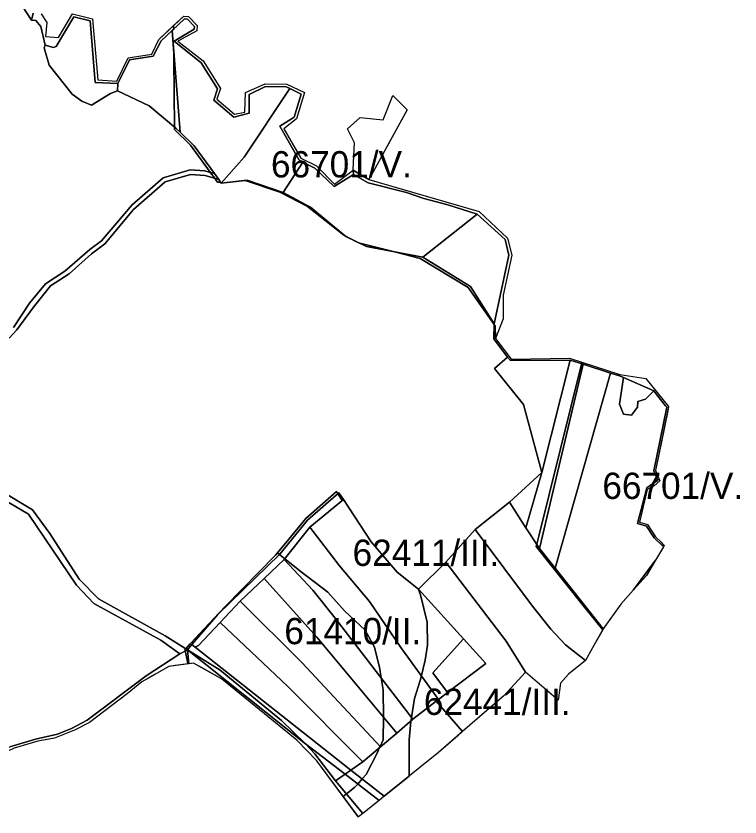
# Model space of a CAD drawing. Extents: x -522079 to -518792, y -1142400 to -1139961.
# Drawn here: x -519204.8 to -518792, y -1141827.7 to -1141371.1 of the extents above; entities that cross this region are included whole.
import ezdxf

# ---------------------------------------------------------------- set-up
doc = ezdxf.new("R2010")
doc.units = 0
for name, color, linetype in [('Hranice parcel', 7, 'Continuous'), ('Parcelní čísla', 7, 'Continuous'), ('Poz předměty', 7, 'Continuous'), ('Vnitřní kresba', 7, 'Continuous'), ('Značky bodu BP', 7, 'Continuous'), ('Značky budov', 7, 'Continuous')]:
    doc.layers.add(name, color=color, linetype=linetype)

msp = doc.modelspace()

# ---------------------------------------------------------------- linework, layer by layer
at = {"layer": 'Hranice parcel'}
msp.add_lwpolyline([(-519206.19, -1141548.7), (-519197.16, -1141534.83), (-519187.98, -1141523.67), (-519176.92, -1141516.46), (-519162.77, -1141504.09), (-519156, -1141499.24), (-519138.46, -1141478.73), (-519120.93, -1141463.32), (-519105.52, -1141458.68), (-519097.28, -1141459.27), (-519091.6, -1141460.78), (-519089.22, -1141464.23), (-519097.02, -1141461.95), (-519105.2, -1141461.4), (-519119.76, -1141465.66), (-519137.74, -1141481.36), (-519154.09, -1141500.95), (-519161.65, -1141506.59), (-519174.38, -1141518.14), (-519185.11, -1141524.98), (-519194.87, -1141536.97), (-519204.3, -1141549.93), (-519208.65, -1141554.69)], dxfattribs=at)
for points in [[(-519215.97, -1141644.42), (-519234.03, -1141639.34), (-519247.24, -1141637.55), (-519267.72, -1141635.03), (-519278.79, -1141629.39), (-519283.88, -1141624.46), (-519281.83, -1141620.82), (-519276.07, -1141627.44), (-519266.93, -1141631.65), (-519236.73, -1141634.83), (-519229.49, -1141636.68), (-519214.22, -1141641.4), (-519195.4, -1141652.58), (-519185.55, -1141666.07), (-519168.83, -1141692.07), (-519157.76, -1141703.36), (-519119.77, -1141724.36), (-519107.07, -1141732.42), (-519111.34, -1141734.71), (-519122.24, -1141726.88), (-519160.32, -1141706.01), (-519170.28, -1141695.6), (-519197.57, -1141654.98)], [(-519100.73, -1141730.04), (-519102.66, -1141730.9), (-519104.58, -1141729.38), (-519089.65, -1141712.19), (-519054.42, -1141677.83), (-519038.58, -1141658.51), (-519020.66, -1141642.94), (-519018.14, -1141646.74), (-519037.2, -1141662.52), (-519051.93, -1141680.89), (-519063.3, -1141691.75), (-519076.93, -1141704.76), (-519088.31, -1141716.77)], [(-519053.38, -1141772.67), (-519088.35, -1141744.1), (-519107.07, -1141732.42), (-519104.58, -1141729.38), (-519102.66, -1141730.9), (-519013.82, -1141800.95), (-519017.2, -1141803.32), (-519039.72, -1141785.92)], [(-519192.31, -1141784.44), (-519205.85, -1141788.49), (-519209.88, -1141790.38), (-519211, -1141789.08), (-519208.31, -1141787.64), (-519193.63, -1141783.33), (-519181.21, -1141780.54), (-519173.18, -1141777.23), (-519164.17, -1141772.59), (-519130.56, -1141747.22), (-519111.34, -1141734.71), (-519107.07, -1141732.42), (-519106.29, -1141740.33), (-519117.64, -1141741.85), (-519132.98, -1141750.7), (-519141.38, -1141757.45), (-519162.82, -1141773.79), (-519171.52, -1141778.29), (-519182.83, -1141782.69)], [(-519053.38, -1141772.67), (-519039.72, -1141785.92), (-519107.07, -1141732.42), (-519088.35, -1141744.1)], [(-518994.87, -1141815.89), (-518997.83, -1141818.27), (-519017.2, -1141803.32), (-519013.82, -1141800.95)]]:
    msp.add_lwpolyline(points, close=True, dxfattribs=at)
at = {"layer": 'Parcelní čísla'}
for points in [[(-519037.2, -1141662.52), (-519020.32, -1141684.47), (-519003.26, -1141704.92), (-518985.35, -1141731.05), (-518963.82, -1141760.65), (-518965.15, -1141761.66), (-518978.59, -1141771.9), (-519022.75, -1141714.32), (-519035.63, -1141698.35), (-519051.93, -1141680.89)], [(-518978.59, -1141771.9), (-518987.69, -1141779.96), (-519033.2, -1141725.1), (-519063.3, -1141691.75), (-519051.93, -1141680.89), (-519035.63, -1141698.35), (-519022.75, -1141714.32)], [(-519063.3, -1141691.75), (-519033.2, -1141725.1), (-518987.69, -1141779.96), (-518996.96, -1141787.68), (-519041.86, -1141739.72), (-519076.93, -1141704.76)], [(-519076.93, -1141704.76), (-519041.86, -1141739.72), (-518996.96, -1141787.68), (-519007.07, -1141796.21), (-519049.77, -1141753.31), (-519088.31, -1141716.77)], [(-519100.73, -1141730.04), (-519088.31, -1141716.77), (-519049.77, -1141753.31), (-519007.07, -1141796.21), (-519013.82, -1141800.95), (-519102.66, -1141730.9)], [(-519034.33, -1141791.67), (-519022.6, -1141807.12), (-519007.06, -1141825.69), (-519009.58, -1141827.71), (-519033.21, -1141795.69), (-519044.72, -1141783.93), (-519087.6, -1141748.94), (-519103.5, -1141739.96), (-519106.29, -1141740.33), (-519107.07, -1141732.42), (-519039.72, -1141785.92)], [(-518978.59, -1141771.9), (-518965.15, -1141761.66), (-518950.14, -1141779.05), (-518963.91, -1141791), (-518994.87, -1141815.89), (-519013.82, -1141800.95), (-519007.07, -1141796.21), (-518996.96, -1141787.68), (-518987.69, -1141779.96)], [(-519039.72, -1141785.92), (-519017.2, -1141803.32), (-519022.6, -1141807.12), (-519034.33, -1141791.67)], [(-519022.6, -1141807.12), (-519017.2, -1141803.32), (-518997.83, -1141818.27), (-519007.06, -1141825.69)]]:
    msp.add_lwpolyline(points, close=True, dxfattribs=at)
at = {"layer": 'Poz předměty'}
for points in [[(-519012.53, -1141459.04), (-519012.34, -1141454.52), (-519011.87, -1141443.33), (-519015.74, -1141435.38), (-519008.63, -1141428.83), (-518995.53, -1141430.25), (-518989.97, -1141416.33), (-518981.74, -1141424.63), (-518994.55, -1141447.83), (-519001.41, -1141460.26), (-519003.59, -1141464.2), (-519005.83, -1141462.95)], [(-518906.3, -1141674.57), (-518881.49, -1141569.59), (-518865.88, -1141574.59), (-518897.41, -1141685.82)], [(-518845.18, -1141639.97), (-518850.48, -1141660.34), (-518845.32, -1141661.82), (-518840.87, -1141668.48), (-518835.69, -1141673.66), (-518840.27, -1141681.38), (-518852.72, -1141698.29), (-518859.88, -1141706.38), (-518869.99, -1141720.5), (-518897.41, -1141685.82), (-518865.88, -1141574.59), (-518860.8, -1141576.22), (-518858.5, -1141577.22), (-518860.72, -1141592.27), (-518858.42, -1141598.04), (-518853.84, -1141598.54), (-518850.43, -1141594.07), (-518850.24, -1141590.84), (-518845.96, -1141589.42), (-518841.19, -1141584.77), (-518839.43, -1141586.95), (-518834.47, -1141593.24), (-518833.75, -1141593.98), (-518841.11, -1141630.32), (-518838.85, -1141635.75)], [(-518853.84, -1141598.54), (-518858.42, -1141598.04), (-518860.72, -1141592.27), (-518858.5, -1141577.22), (-518841.19, -1141584.77), (-518845.96, -1141589.42), (-518850.24, -1141590.84), (-518850.43, -1141594.07)], [(-519037.2, -1141662.52), (-519018.14, -1141646.74), (-519002.22, -1141670.75), (-518987.45, -1141688.21), (-518975.25, -1141697.8), (-518949.63, -1141726.06), (-518967.09, -1141745.55), (-518958.75, -1141756.79), (-518963.82, -1141760.65), (-518985.35, -1141731.05), (-519003.26, -1141704.92), (-519020.32, -1141684.47)], [(-518845.39, -1141690.02), (-518852.72, -1141698.29), (-518840.27, -1141681.38)]]:
    msp.add_lwpolyline(points, close=True, dxfattribs=at)
at = {"layer": 'Vnitřní kresba'}
for points in [[(-519194.96, -1141369.43), (-519195.98, -1141373.38), (-519201.22, -1141365.24)], [(-519190.42, -1141369.81), (-519187.2, -1141374.82), (-519188.01, -1141382.78), (-519180.54, -1141383.29), (-519172.49, -1141369.75), (-519161.16, -1141372.68), (-519158.19, -1141407.51), (-519147.23, -1141408.12), (-519140.85, -1141394.82), (-519127.25, -1141392.73), (-519123.4, -1141384.39), (-519109.18, -1141371.2), (-519106.36, -1141371.37), (-519101.55, -1141376.47), (-519101.7, -1141379.43), (-519112.59, -1141385.36), (-519098.12, -1141396.65), (-519088.18, -1141412.32), (-519090.32, -1141418.48), (-519080.26, -1141427.02), (-519074.35, -1141425.83), (-519073.85, -1141414.66), (-519062.78, -1141409.81), (-519050.33, -1141409.98), (-519040.39, -1141414.74), (-519044.82, -1141429.69), (-519052, -1141435.32), (-519042.3, -1141452.19), (-519033.46, -1141456.53), (-519023.29, -1141466.86), (-519012.53, -1141459.04), (-519012.3, -1141461.46), (-519023.36, -1141468.17), (-519034.35, -1141457.76), (-519041.21, -1141454.39), (-519043.38, -1141453.33), (-519054.33, -1141433.88), (-519046.13, -1141428.81), (-519042.19, -1141415.54), (-519048.65, -1141412.42), (-519050.68, -1141411.48), (-519062.49, -1141411.31), (-519071.92, -1141415.76), (-519071.77, -1141426.39), (-519080.67, -1141428.64), (-519092.08, -1141418.96), (-519089.83, -1141412.51), (-519099.25, -1141397.67), (-519114.56, -1141385.44), (-519103.16, -1141378.52), (-519103.08, -1141377.03), (-519107.04, -1141372.83), (-519108.63, -1141372.74), (-519115.78, -1141379.37), (-519122.09, -1141385.22), (-519126.66, -1141393.95), (-519140.08, -1141396.13), (-519146.7, -1141409.56), (-519159.57, -1141408.94), (-519162.56, -1141373.86), (-519171.77, -1141371.48), (-519181.87, -1141388.46), (-519183.39, -1141388.93), (-519188.19, -1141387.74), (-519190.53, -1141377.07), (-519193.48, -1141373.59), (-519195.98, -1141373.38), (-519194.96, -1141369.43)]]:
    msp.add_lwpolyline(points, dxfattribs=at)
msp.add_lwpolyline([(-518841.19, -1141584.77), (-518858.5, -1141577.22), (-518860.8, -1141576.22), (-518865.88, -1141574.59), (-518881.49, -1141569.59), (-518888.92, -1141567.21), (-518922.95, -1141567.54), (-518924.52, -1141565.49), (-518932.45, -1141555.15), (-518932.13, -1141546.59), (-518923.9, -1141507.34), (-518925.88, -1141498.42), (-518941.87, -1141484.11), (-518958.68, -1141478.71), (-518972.22, -1141475.1), (-518982.13, -1141471.67), (-519003.93, -1141466.26), (-519012.3, -1141461.46), (-519012.53, -1141459.04), (-519005.83, -1141462.95), (-519003.59, -1141464.2), (-518940.71, -1141482.48), (-518924.49, -1141497.8), (-518922.06, -1141507.35), (-518927.02, -1141530.23), (-518927.11, -1141543.74), (-518931.43, -1141555), (-518922.51, -1141566.63), (-518889.18, -1141566.18), (-518860.53, -1141575.36), (-518845.76, -1141577.71), (-518832.78, -1141593.74), (-518840.17, -1141630.23), (-518837.74, -1141636.08), (-518840.9, -1141638.87), (-518844.96, -1141640.98), (-518849.41, -1141659.71), (-518844.75, -1141661.05), (-518840.16, -1141667.91), (-518837.05, -1141671.02), (-518835.83, -1141672.48), (-518835.18, -1141672.79), (-518835.69, -1141673.66), (-518840.87, -1141668.48), (-518845.32, -1141661.82), (-518850.48, -1141660.34), (-518845.18, -1141639.97), (-518838.85, -1141635.75), (-518841.11, -1141630.32), (-518833.75, -1141593.98), (-518834.47, -1141593.24), (-518839.43, -1141586.95)], close=True, dxfattribs=at)
at = {"layer": 'Značky bodu BP'}
msp.add_lwpolyline([(-519190.42, -1141369.81), (-519187.2, -1141374.82), (-519188.01, -1141382.78), (-519180.54, -1141383.29), (-519172.49, -1141369.75), (-519161.16, -1141372.68), (-519158.19, -1141407.51), (-519147.23, -1141408.12), (-519140.85, -1141394.82), (-519127.25, -1141392.73), (-519123.4, -1141384.39), (-519114.91, -1141376.51), (-519114.89, -1141378.55), (-519115.78, -1141379.37), (-519114.79, -1141392.16), (-519114.76, -1141395.66), (-519114.45, -1141434.34), (-519114.44, -1141435.73), (-519105.32, -1141444.7), (-519093.99, -1141460.14), (-519093.82, -1141460.38), (-519091.51, -1141463.56), (-519091.05, -1141464.19), (-519089.82, -1141465.88), (-519088.81, -1141465.79), (-519088.18, -1141465.73), (-519087.76, -1141466.33), (-519074.1, -1141464.81), (-519054.45, -1141471.42), (-519038.62, -1141479.75), (-519017.88, -1141496.05), (-519017.44, -1141496.27), (-519011.01, -1141499.58), (-519009.72, -1141500.25), (-519009.51, -1141500.31), (-518988.31, -1141505.68), (-518974.38, -1141509.22), (-518947.06, -1141525.93), (-518932.14, -1141546.87), (-518931.94, -1141547.15), (-518931.68, -1141547.51), (-518931.43, -1141555), (-518922.51, -1141566.63), (-518889.18, -1141566.18), (-518882.12, -1141568.44), (-518882.2, -1141568.75), (-518882.42, -1141569.64), (-518906.77, -1141667.62), (-518907.9, -1141672.18), (-518908.23, -1141673.5), (-518881.36, -1141707.08), (-518870.25, -1141720.96), (-518876.08, -1141731.29), (-518880.1, -1141738.42), (-518889.83, -1141746.28), (-518894.38, -1141751.49), (-518895.73, -1141761.19), (-518914.26, -1141745.22), (-518926.6, -1141758.63), (-518950.14, -1141779.05), (-518965.15, -1141761.66), (-518963.82, -1141760.65), (-518958.75, -1141756.79), (-518967.09, -1141745.55), (-518949.63, -1141726.06), (-518975.25, -1141697.8), (-518987.45, -1141688.21), (-519002.22, -1141670.75), (-519018.14, -1141646.74), (-519018.79, -1141647.28), (-519019.83, -1141645.67), (-519021.25, -1141643.45), (-519022.09, -1141642.15), (-519039.51, -1141657.59), (-519049.19, -1141669.31), (-519055.71, -1141677.2), (-519056.76, -1141678.48), (-519085.6, -1141707.64), (-519097.6, -1141720.57), (-519105.12, -1141728.66), (-519105.58, -1141729.16), (-519108.03, -1141731.81), (-519108.23, -1141732.02), (-519108.46, -1141732.26), (-519108.37, -1141732.68), (-519108.29, -1141733.07), (-519107.07, -1141739.1), (-519106.85, -1141740.41), (-519112.49, -1141741.16), (-519114, -1141741.36), (-519117.64, -1141741.85), (-519125.57, -1141746.42), (-519129.17, -1141748.5), (-519132.98, -1141750.7), (-519141.38, -1141757.45), (-519162.82, -1141773.79), (-519171.52, -1141778.29), (-519182.83, -1141782.69), (-519185.92, -1141783.26), (-519192.31, -1141784.44), (-519205.85, -1141788.49)], dxfattribs=at)
for points in [[(-519109.18, -1141371.2), (-519106.36, -1141371.37), (-519101.55, -1141376.47), (-519101.7, -1141379.43), (-519112.59, -1141385.36), (-519098.12, -1141396.65), (-519088.18, -1141412.32), (-519090.32, -1141418.48), (-519080.26, -1141427.02), (-519074.35, -1141425.83), (-519073.85, -1141414.66), (-519062.78, -1141409.81), (-519050.33, -1141409.98), (-519040.39, -1141414.74), (-519044.82, -1141429.69), (-519052, -1141435.32), (-519042.3, -1141452.19), (-519033.46, -1141456.53), (-519023.29, -1141466.86), (-519012.53, -1141459.04), (-519012.34, -1141454.52), (-519011.87, -1141443.33), (-519015.74, -1141435.38), (-519008.63, -1141428.83), (-518995.53, -1141430.25), (-518989.97, -1141416.33), (-518981.74, -1141424.63), (-518994.04, -1141446.9), (-518994.26, -1141447.3), (-518994.55, -1141447.83), (-519001.41, -1141460.26), (-519003.59, -1141464.2), (-518940.71, -1141482.48), (-518924.49, -1141497.8), (-518922.06, -1141507.35), (-518927.02, -1141530.23), (-518927.11, -1141543.74), (-518931.43, -1141555), (-518931.68, -1141547.51), (-518931.94, -1141547.15), (-518932.14, -1141546.87), (-518947.06, -1141525.93), (-518974.38, -1141509.22), (-518988.31, -1141505.68), (-519009.51, -1141500.31), (-519009.72, -1141500.25), (-519011.01, -1141499.58), (-519017.44, -1141496.27), (-519017.88, -1141496.05), (-519038.62, -1141479.75), (-519054.45, -1141471.42), (-519074.1, -1141464.81), (-519087.76, -1141466.33), (-519088.18, -1141465.73), (-519088.81, -1141465.79), (-519089.82, -1141465.88), (-519091.05, -1141464.19), (-519091.51, -1141463.56), (-519093.82, -1141460.38), (-519093.99, -1141460.14), (-519105.32, -1141444.7), (-519114.44, -1141435.73), (-519114.45, -1141434.34), (-519114.76, -1141395.66), (-519114.79, -1141392.16), (-519115.78, -1141379.37), (-519114.89, -1141378.55), (-519114.91, -1141376.51)], [(-518832.78, -1141593.74), (-518833.26, -1141596.09), (-518837.06, -1141614.85), (-518840.17, -1141630.23), (-518837.74, -1141636.08), (-518840.9, -1141638.87), (-518844.96, -1141640.98), (-518849.41, -1141659.71), (-518844.75, -1141661.05), (-518840.16, -1141667.91), (-518837.05, -1141671.02), (-518835.83, -1141672.48), (-518835.18, -1141672.79), (-518835.69, -1141673.66), (-518840.27, -1141681.38), (-518845.39, -1141690.02), (-518852.72, -1141698.29), (-518859.88, -1141706.38), (-518869.99, -1141720.5), (-518870.25, -1141720.96), (-518881.36, -1141707.08), (-518908.23, -1141673.5), (-518907.9, -1141672.18), (-518906.77, -1141667.62), (-518882.42, -1141569.64), (-518882.2, -1141568.75), (-518882.12, -1141568.44), (-518860.53, -1141575.36), (-518845.76, -1141577.71)], [(-519009.65, -1141827.61), (-519018.17, -1141816.07), (-519016.34, -1141814.6), (-519011.8, -1141810.95), (-519011.11, -1141810.19), (-519009.96, -1141808.91), (-519007.37, -1141806.04), (-519005.08, -1141803.51), (-518999.07, -1141791.8), (-518997.47, -1141788.11), (-518997.18, -1141787.44), (-518995.54, -1141783.65), (-518995.18, -1141770.9), (-518995.54, -1141755.28), (-518996.62, -1141748.38), (-518997.57, -1141742.39), (-518997.66, -1141741.8), (-519000.49, -1141730.81), (-519005.79, -1141721.24), (-519017.45, -1141710.24), (-519027, -1141699.6), (-519042.2, -1141687.9), (-519051.59, -1141680.46), (-519054.64, -1141678.04), (-519055.71, -1141677.2), (-519049.19, -1141669.31), (-519039.51, -1141657.59), (-519022.09, -1141642.15), (-519021.25, -1141643.45), (-519019.83, -1141645.67), (-519018.79, -1141647.28), (-519018.14, -1141646.74), (-519002.22, -1141670.75), (-518987.45, -1141688.21), (-518975.25, -1141697.8), (-518975.03, -1141698.5), (-518974.24, -1141700.97), (-518970.44, -1141716.62), (-518970.09, -1141729.75), (-518971.5, -1141738.26), (-518973.65, -1141747.14), (-518974.33, -1141749.96), (-518977.51, -1141760.25), (-518979.25, -1141771.03), (-518979.53, -1141772.73), (-518979.63, -1141773.36), (-518980.69, -1141783.65), (-518980.69, -1141792.87), (-518980.69, -1141800.95), (-518980.69, -1141803.93), (-518980.69, -1141804.49), (-518994.87, -1141815.89), (-518997.83, -1141818.27), (-519007.06, -1141825.69), (-519009.58, -1141827.71)], [(-519103.5, -1141739.96), (-519104.73, -1141740.12), (-519106.29, -1141740.33), (-519106.85, -1141740.41), (-519107.07, -1141739.1), (-519108.29, -1141733.07), (-519108.37, -1141732.68), (-519108.46, -1141732.26), (-519108.23, -1141732.02), (-519108.03, -1141731.81), (-519105.58, -1141729.16), (-519105.12, -1141728.66), (-519097.6, -1141720.57), (-519085.6, -1141707.64), (-519056.76, -1141678.48), (-519055.71, -1141677.2), (-519054.64, -1141678.04), (-519051.59, -1141680.46), (-519042.2, -1141687.9), (-519027, -1141699.6), (-519017.45, -1141710.24), (-519005.79, -1141721.24), (-519000.49, -1141730.81), (-518997.66, -1141741.8), (-518997.57, -1141742.39), (-518996.62, -1141748.38), (-518995.54, -1141755.28), (-518995.18, -1141770.9), (-518995.54, -1141783.65), (-518997.18, -1141787.44), (-518997.47, -1141788.11), (-518999.07, -1141791.8), (-519005.08, -1141803.51), (-519007.37, -1141806.04), (-519009.96, -1141808.91), (-519011.11, -1141810.19), (-519011.8, -1141810.95), (-519016.34, -1141814.6), (-519018.17, -1141816.07), (-519033.21, -1141795.69), (-519044.72, -1141783.93), (-519087.6, -1141748.94), (-519096.93, -1141743.67), (-519096.96, -1141743.65)], [(-518952.9, -1141781.45), (-518963.91, -1141791), (-518994.87, -1141815.89), (-518980.69, -1141804.49), (-518980.69, -1141803.93), (-518980.69, -1141800.95), (-518980.69, -1141792.87), (-518980.69, -1141783.65), (-518979.63, -1141773.36), (-518979.53, -1141772.73), (-518979.25, -1141771.03), (-518977.51, -1141760.25), (-518974.33, -1141749.96), (-518973.65, -1141747.14), (-518971.5, -1141738.26), (-518970.09, -1141729.75), (-518970.44, -1141716.62), (-518974.24, -1141700.97), (-518975.03, -1141698.5), (-518975.25, -1141697.8), (-518949.63, -1141726.06), (-518967.09, -1141745.55), (-518958.75, -1141756.79), (-518963.82, -1141760.65), (-518965.15, -1141761.66), (-518950.14, -1141779.05), (-518952.9, -1141781.44)]]:
    msp.add_lwpolyline(points, close=True, dxfattribs=at)
at = {"layer": 'Značky budov'}
for points in [[(-519201.22, -1141365.24), (-519195.98, -1141373.38), (-519193.48, -1141373.59), (-519190.53, -1141377.07), (-519188.19, -1141387.74), (-519188.81, -1141389.21), (-519185.95, -1141399.11), (-519172.73, -1141415.6), (-519167.27, -1141419.59), (-519161.79, -1141421.83), (-519150.96, -1141415.24), (-519146.88, -1141413.75), (-519128.84, -1141422.33), (-519113.73, -1141434.94), (-519111.28, -1141437.32), (-519103.24, -1141445.12), (-519091.6, -1141460.78), (-519097.28, -1141459.27), (-519105.52, -1141458.68), (-519120.93, -1141463.32), (-519138.46, -1141478.73), (-519156, -1141499.24), (-519162.77, -1141504.09), (-519176.92, -1141516.46), (-519187.98, -1141523.67), (-519197.16, -1141534.83), (-519206.19, -1141548.7)], [(-519208.65, -1141554.69), (-519204.3, -1141549.93), (-519194.87, -1141536.97), (-519185.11, -1141524.98), (-519174.38, -1141518.14), (-519161.65, -1141506.59), (-519154.09, -1141500.95), (-519137.74, -1141481.36), (-519119.76, -1141465.66), (-519105.2, -1141461.4), (-519097.02, -1141461.95), (-519089.22, -1141464.23), (-519087.76, -1141466.33), (-519073.04, -1141464.69), (-519052.51, -1141471.71), (-519036.96, -1141480), (-519016.8, -1141496.81), (-519004.9, -1141502.52), (-518972.83, -1141508.64), (-518945.58, -1141525.34), (-518932.13, -1141546.59), (-518932.45, -1141555.15), (-518924.52, -1141565.49), (-518931.99, -1141572.05), (-518915.44, -1141592.52), (-518904.97, -1141631.37), (-518923.48, -1141648.24), (-518942.97, -1141663.76), (-518959.67, -1141682.43), (-518975.25, -1141697.8), (-518987.45, -1141688.21), (-519002.22, -1141670.75), (-519018.14, -1141646.74), (-519020.66, -1141642.94), (-519038.58, -1141658.51), (-519054.42, -1141677.83), (-519089.65, -1141712.19), (-519104.58, -1141729.38), (-519107.07, -1141732.42), (-519119.77, -1141724.36), (-519157.76, -1141703.36), (-519168.83, -1141692.07), (-519185.55, -1141666.07), (-519195.4, -1141652.58), (-519214.22, -1141641.4)], [(-519215.97, -1141644.42), (-519197.57, -1141654.98), (-519170.28, -1141695.6), (-519160.32, -1141706.01), (-519122.24, -1141726.88), (-519111.34, -1141734.71), (-519130.56, -1141747.22), (-519164.17, -1141772.59), (-519173.18, -1141777.23), (-519181.21, -1141780.54), (-519193.63, -1141783.33), (-519208.31, -1141787.64)]]:
    msp.add_lwpolyline(points, dxfattribs=at)
for points in [[(-519167.27, -1141419.59), (-519172.73, -1141415.6), (-519185.95, -1141399.11), (-519188.81, -1141389.21), (-519188.19, -1141387.74), (-519183.39, -1141388.93), (-519181.87, -1141388.46), (-519171.77, -1141371.48), (-519162.56, -1141373.86), (-519159.57, -1141408.94), (-519146.7, -1141409.56), (-519146.88, -1141413.75), (-519150.96, -1141415.24), (-519161.79, -1141421.83)], [(-519115.78, -1141379.37), (-519108.63, -1141372.74), (-519107.04, -1141372.83), (-519103.08, -1141377.03), (-519103.16, -1141378.52), (-519114.56, -1141385.44), (-519099.25, -1141397.67), (-519089.83, -1141412.51), (-519092.08, -1141418.96), (-519080.67, -1141428.64), (-519071.77, -1141426.39), (-519071.92, -1141415.76), (-519062.49, -1141411.31), (-519050.68, -1141411.48), (-519048.65, -1141412.42), (-519074.76, -1141451.52), (-519087.76, -1141466.33), (-519089.22, -1141464.23), (-519091.6, -1141460.78), (-519103.24, -1141445.12), (-519111.28, -1141437.32)], [(-519113.73, -1141434.94), (-519128.84, -1141422.33), (-519146.88, -1141413.75), (-519146.7, -1141409.56), (-519140.08, -1141396.13), (-519126.66, -1141393.95), (-519122.09, -1141385.22), (-519115.78, -1141379.37), (-519111.28, -1141437.32)], [(-519048.65, -1141412.42), (-519042.19, -1141415.54), (-519046.13, -1141428.81), (-519054.33, -1141433.88), (-519043.38, -1141453.33), (-519041.21, -1141454.39), (-519052.51, -1141471.71), (-519073.04, -1141464.69), (-519087.76, -1141466.33), (-519074.76, -1141451.52)], [(-518941.87, -1141484.11), (-518972.83, -1141508.64), (-519004.9, -1141502.52), (-519016.8, -1141496.81), (-519036.96, -1141480), (-519052.51, -1141471.71), (-519041.21, -1141454.39), (-519034.35, -1141457.76), (-519023.36, -1141468.17), (-519012.3, -1141461.46), (-519003.93, -1141466.26), (-518982.13, -1141471.67), (-518972.22, -1141475.1), (-518958.68, -1141478.71)], [(-518932.13, -1141546.59), (-518945.58, -1141525.34), (-518972.83, -1141508.64), (-518941.87, -1141484.11), (-518925.88, -1141498.42), (-518923.9, -1141507.34)], [(-518888.92, -1141567.21), (-518904.97, -1141631.37), (-518915.44, -1141592.52), (-518931.99, -1141572.05), (-518924.52, -1141565.49), (-518922.95, -1141567.54)], [(-518906.3, -1141674.57), (-518914.15, -1141662.84), (-518904.97, -1141631.37), (-518888.92, -1141567.21), (-518881.49, -1141569.59)], [(-518904.97, -1141631.37), (-518914.15, -1141662.84), (-518923.48, -1141648.24)], [(-518942.97, -1141663.76), (-518923.48, -1141648.24), (-518914.15, -1141662.84), (-518906.3, -1141674.57), (-518897.41, -1141685.82), (-518869.99, -1141720.5), (-518876.08, -1141731.29), (-518880.1, -1141738.42), (-518891.54, -1141729.55), (-518899.83, -1141720.66), (-518910.37, -1141707.51)], [(-518925.33, -1141727.39), (-518959.67, -1141682.43), (-518942.97, -1141663.76), (-518910.37, -1141707.51), (-518899.83, -1141720.66), (-518891.54, -1141729.55), (-518880.1, -1141738.42), (-518889.83, -1141746.28), (-518894.38, -1141751.49), (-518895.73, -1141761.19), (-518914.26, -1141745.22)], [(-518965.15, -1141761.66), (-518963.82, -1141760.65), (-518958.75, -1141756.79), (-518936.87, -1141740.13), (-518949.63, -1141726.06), (-518975.25, -1141697.8), (-518959.67, -1141682.43), (-518925.33, -1141727.39), (-518914.26, -1141745.22), (-518926.6, -1141758.63), (-518950.14, -1141779.05)], [(-518958.75, -1141756.79), (-518967.09, -1141745.55), (-518949.63, -1141726.06), (-518936.87, -1141740.13)]]:
    msp.add_lwpolyline(points, close=True, dxfattribs=at)

# ---------------------------------------------------------------- texts
at = {"layer": 'Značky bodu BP'}
for s, rotation, p in [('66701/V.', 0, (-519059.42, -1141463.1)), ('66701/V.', 360, (-518870.51, -1141646.4)), ('62411/III.', 360, (-519012.9, -1141684.59)), ('61410/II.', 360, (-519051.82, -1141729.21)), ('62441/III.', 0, (-518972.25, -1141769.53))]:
    msp.add_text(s, height=15, rotation=rotation, dxfattribs=at).set_placement(p)

doc.saveas('drawing.dxf')
